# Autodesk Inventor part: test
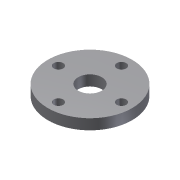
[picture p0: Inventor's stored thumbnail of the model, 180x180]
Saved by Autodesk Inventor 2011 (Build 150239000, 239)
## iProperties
Shininess: 65.0
Angle Display Precision: 2
Document Length Units: 11269
Document Angle Units: 11279
Document Time Units: 11290
Document Mass Units: 11283
Document Length Units Precision: 3
Document Angle Units Precision: 2
Created: 2002-02
Part Number: test
Document SubType Name: Modeling
Designer: ***
Density: 1 g/cm^3
Density: 0.0
Volumn: 0.0
Area: 0.0
PropertySet Name: Model Information
Control State: 0
Master: False
Checked Out: False
Author: ***
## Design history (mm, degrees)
sketch "Sketch1"
  geometry: C1 r 100 at (0, 0); C2 r 28 at (0, 0)
  constraints: 2 centre point, 1 coincident
  dimensions: "d0" = 200 diameter of C1; "d1" = 56 diameter of C2
extrude "Extrusion1" new body sketch "Sketch1" stored distance "d2" = 25; taper "d3" = 0 deg
sketch "Sketch2"
  geometry: 2 further points
  dimensions: "d4" = 75 distance of point (0, 0) point (-75, 0)
hole "Hole1" sketch "Sketch2" at (-75, 0) diameter "d5" = 22.3; stored, may be unused: countersink angle "d9" = 82 deg, drill point angle "d11" = 118 deg; dims "d6" = 6, "d7" = 4, "d8" = 2, "d10" = 8
pattern_circular "Circular Pattern1" dims angle "d14" = 360 deg
body "Solid1"
